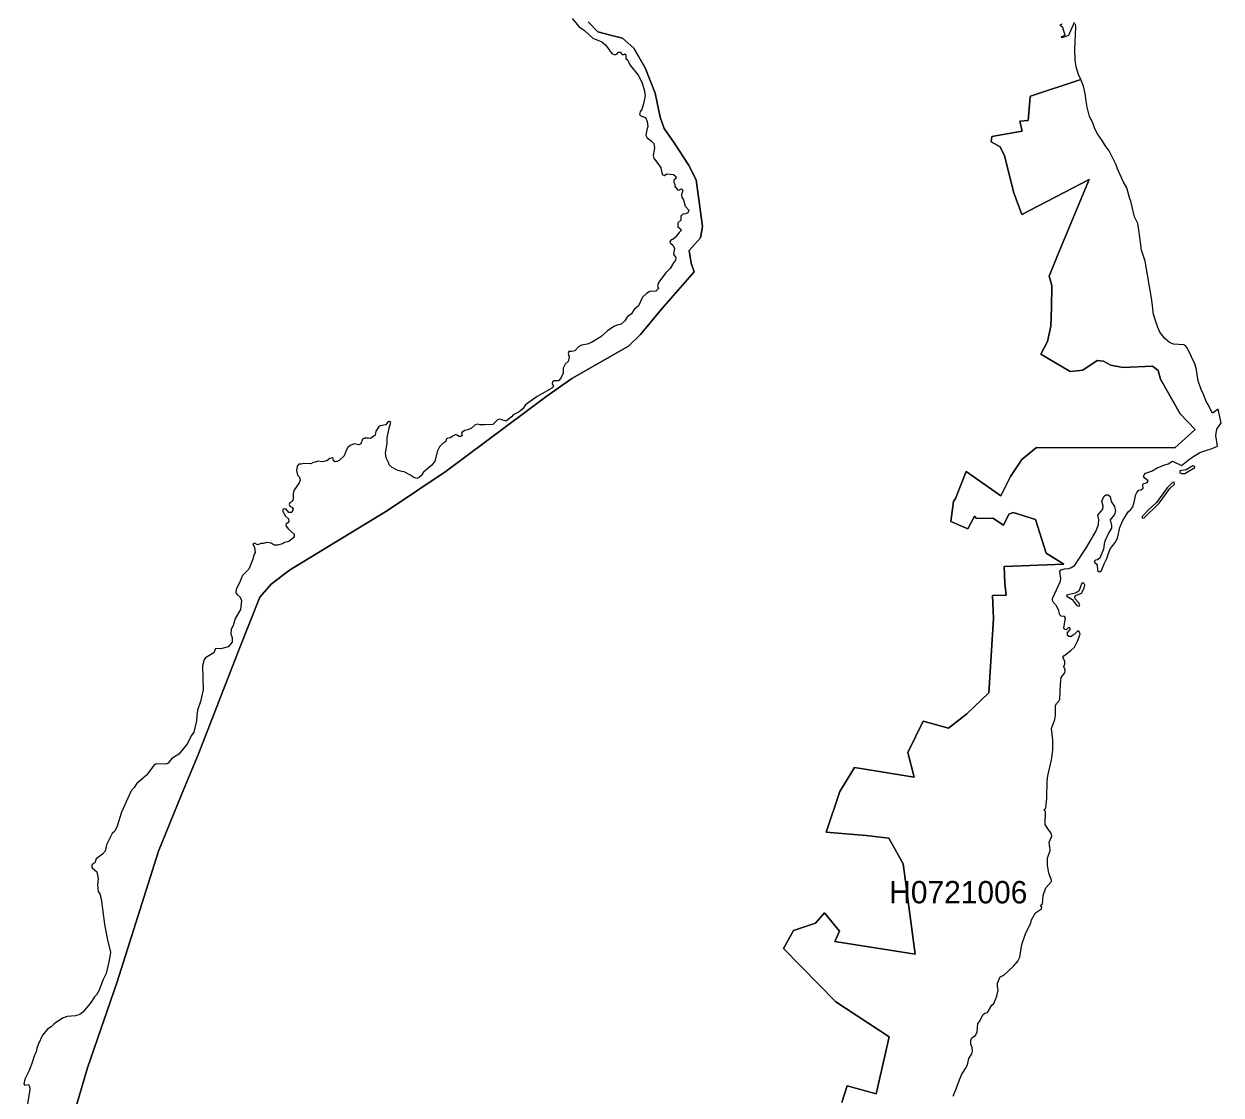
# Model space of a CAD drawing. Extents: x 369010 to 739155, y 6377141 to 6616555.
# Drawn here: x 392519 to 397868, y 6441595 to 6446383 of the extents above; entities that cross this region are included whole.
import ezdxf
from ezdxf.enums import TextEntityAlignment as Align

# ---------------------------------------------------------------- set-up
doc = ezdxf.new("R2010")
doc.units = 0
doc.header["$LTSCALE"] = 40
doc.layers.add('1', color=7, linetype='Continuous', lineweight=13)
doc.layers.add('2', color=7, linetype='Continuous')

msp = doc.modelspace()

# ---------------------------------------------------------------- linework, layer by layer
at = {"layer": '1'}
for points in [[(394968.85, 6446407.72), (395000.13, 6446371.14), (395023.79, 6446353.93), (395061.86, 6446319.18), (395101.08, 6446303.29), (395118.3, 6446289.55), (395145.77, 6446251.15), (395160.17, 6446246.02), (395169.6, 6446250.49), (395175.89, 6446257.77), (395183.84, 6446257.44), (395193.1, 6446247.35), (395199.39, 6446246.85), (395204.52, 6446250), (395208.5, 6446246.02), (395208.17, 6446229.14), (395217.1, 6446221.03), (395227.36, 6446201.01), (395263.77, 6446154.33), (395279.99, 6446123.39), (395290.92, 6446090.78), (395294.89, 6446062.48), (395288.43, 6446026.9), (395279.5, 6446001.24), (395272.05, 6445990.65), (395270.39, 6445979.07), (395275.53, 6445972.78), (395296.71, 6445964.83), (395304.16, 6445947.95), (395306.64, 6445925.28), (395301.84, 6445910.22), (395298.7, 6445886.88), (395303.5, 6445874.14), (395323.52, 6445859.74), (395333.29, 6445848.32), (395337.26, 6445830.28), (395330.97, 6445795.85), (395333.29, 6445783.61), (395341.07, 6445772.68), (395356.79, 6445754.15), (395365.39, 6445740.08), (395371.68, 6445709.96), (395380.79, 6445706.32), (395391.38, 6445713.76), (395407.43, 6445711.11), (395422, 6445709.79), (395432.09, 6445702.01), (395432.92, 6445693.41), (395422.99, 6445685.13), (395422.66, 6445675.86), (395427.13, 6445666.43), (395427.46, 6445658.48), (395438.88, 6445641.93), (395445.5, 6445639.78), (395457.58, 6445646.24), (395463.21, 6445639.62), (395456.75, 6445621.25), (395459.23, 6445608.01), (395467.01, 6445596.92), (395473.3, 6445568.78), (395489.69, 6445551.4), (395485.38, 6445539.65), (395474.79, 6445534.19), (395463.04, 6445532.54), (395454.93, 6445524.76), (395454.1, 6445505.56), (395440.37, 6445494.14), (395440.7, 6445476.43), (395453.28, 6445467.49), (395455.26, 6445459.71), (395446.33, 6445451.77), (395429.28, 6445429.1), (395418.85, 6445420.32), (395410.58, 6445418.5), (395404.62, 6445411.06), (395406.11, 6445404.77), (395419.18, 6445394.51), (395426.63, 6445381.6), (395421.5, 6445352.63), (395431.43, 6445339.89), (395430.93, 6445326.65), (395421.5, 6445316.06), (395406.6, 6445290.07), (395385.42, 6445268.89), (395355.63, 6445228.51), (395350.17, 6445214.44), (395355.3, 6445201.03), (395342.72, 6445189.45), (395315.91, 6445186.63), (395300.68, 6445178.03), (395283.47, 6445161.48), (395265.26, 6445123.58), (395245.4, 6445106.2), (395232.83, 6445086.67)], [(392710.88, 6441402.71), (392803.72, 6441716.34), (392935.3, 6442101.31), (393120.99, 6442685.87), (393221.62, 6442933.79), (393299.08, 6443120.32), (393480.97, 6443588.86), (393573.81, 6443821.22), (393624.13, 6443879.32), (393705.39, 6443941.22), (394144.31, 6444207.51), (394406.3, 6444384.43), (394851.17, 6444715.94), (394967.85, 6444798.03), (395220.41, 6444943.18), (395274.04, 6444994.48), (395368.7, 6445108.02), (395513.85, 6445275.34), (395501.27, 6445313.24), (395491.67, 6445370.18), (395542.15, 6445426.94), (395551.75, 6445477.42), (395522.62, 6445687.12), (395488.03, 6445753.48), (395424.81, 6445851.3), (395380.62, 6445915.68), (395361.75, 6445966.32), (395339.58, 6446073.57), (395295.55, 6446187.27), (395244.91, 6446275.65), (395194.43, 6446319.84), (395140.81, 6446332.58), (395084.04, 6446348.31), (395039.85, 6446392.49)], [(395039.85, 6446392.49), (395084.04, 6446348.31), (395140.81, 6446332.58), (395194.43, 6446319.84), (395244.91, 6446275.65), (395295.55, 6446187.27), (395339.58, 6446073.57), (395361.75, 6445966.32), (395380.62, 6445915.68), (395424.81, 6445851.3), (395488.03, 6445753.48), (395522.62, 6445687.12), (395551.75, 6445477.42), (395542.15, 6445426.94), (395491.67, 6445370.18), (395501.27, 6445313.24), (395513.85, 6445275.34), (395368.7, 6445108.02)], [(397430.06, 6444847.51), (397376.6, 6444857.28), (397342.67, 6444876.15), (397315.53, 6444878.3), (397250.15, 6444834.94), (397193.55, 6444829.47), (397062.8, 6444907.59), (397092.43, 6444964.03), (397107.49, 6445031.89), (397110.8, 6445113.81), (397111.79, 6445214.44), (397100.04, 6445255.32), (397137.28, 6445348.16), (397278.79, 6445687.61), (396978.73, 6445532.04), (396942.65, 6445628.86), (396900.11, 6445793.37), (396880.91, 6445834.25), (396841.52, 6445856.26), (396843.68, 6445880.26), (396979.89, 6445904.09), (396969.13, 6445949.11), (397006.37, 6445952.09), (397015.97, 6446057.85), (397016.3, 6446060.33), (397241.55, 6446134.31), (397232.11, 6446157.64), (397220.69, 6446191.74), (397216.89, 6446221.69), (397215.73, 6446270.68), (397220.03, 6446368.66), (397218.21, 6446384.05)], [(397211.92, 6446389.35), (397186.1, 6446332.42), (397157.14, 6446321.99), (397155.15, 6446327.29), (397172.37, 6446333.91), (397160.29, 6446370.98), (397154.82, 6446371.31), (397150.35, 6446374.45), (397151.18, 6446380.25), (397157.14, 6446382.23), (397158.63, 6446384.88)], [(397241.55, 6446134.31), (397016.3, 6446060.33), (397015.97, 6446057.85), (397006.37, 6445952.09), (396969.13, 6445949.11), (396979.89, 6445904.09), (396843.68, 6445880.26), (396841.52, 6445856.26), (396880.91, 6445834.25), (396900.11, 6445793.37), (396942.65, 6445628.86), (396978.73, 6445532.04), (397278.79, 6445687.61), (397137.28, 6445348.16), (397100.04, 6445255.32), (397111.79, 6445214.44), (397110.8, 6445113.81), (397107.49, 6445031.89), (397092.43, 6444964.03), (397062.8, 6444907.59), (397193.55, 6444829.47), (397250.15, 6444834.94), (397315.53, 6444878.3), (397342.67, 6444876.15), (397376.6, 6444857.28), (397430.06, 6444847.51), (397562.13, 6444853.47), (397587.78, 6444833.94), (397597.55, 6444795.22), (397685.26, 6444640.97), (397753.29, 6444570.13), (397662.09, 6444487.71), (397044.1, 6444489.86), (396977.9, 6444436.07), (396927.42, 6444360.77), (396884.39, 6444273.22), (396729.81, 6444383.28), (396682.31, 6444262.13), (396672.54, 6444248.22), (396661.29, 6444158.85), (396736.26, 6444126.08), (396766.39, 6444182.35), (396776.32, 6444172.59), (396849.3, 6444174.08), (396896.64, 6444142.8), (396920.14, 6444192.45), (396940.16, 6444199.4), (397038.97, 6444168.62), (397087.3, 6444017.51), (397166.24, 6443968.85), (396899.95, 6443957.6), (396902.26, 6443882.3), (396908.55, 6443829.33), (396847.65, 6443827.84), (396852.12, 6443725.56), (396831.43, 6443393.07), (396732.13, 6443299.23), (396649.87, 6443234.84), (396537.82, 6443265.96), (396468.97, 6443126.94), (396497.28, 6443015.39), (396230.81, 6443059.74), (396164.94, 6442952.33), (396104.37, 6442769.78), (396282.95, 6442755.54), (396384.07, 6442743.96), (396447.46, 6442628.44), (396502.08, 6442225.1), (396142.1, 6442280.88), (396162.96, 6442326.89), (396095.93, 6442409.14), (396055.88, 6442363.13), (395957.73, 6442331.03), (395913.05, 6442250.26), (396146.41, 6442012.1), (396385.89, 6441855.86), (396327.97, 6441600.66), (396197.05, 6441635.58), (396173.22, 6441561.93)], [(397374.45, 6444038.2), (397394.64, 6444065.84), (397405.23, 6444084.04), (397415.49, 6444131.88), (397429.89, 6444163.82), (397453.23, 6444202.55), (397465.31, 6444211.98), (397473.75, 6444224.72), (397480.87, 6444244.75), (397487.49, 6444280.33), (397491.79, 6444288.61), (397500.56, 6444298.87), (397512.15, 6444300.19), (397521.08, 6444308.47), (397518.77, 6444318.23), (397520.26, 6444328.16), (397538.96, 6444334.12), (397542.43, 6444340.41), (397521.91, 6444357.95), (397525.06, 6444368.05), (397531.51, 6444374.84), (397557.16, 6444384.27), (397582.49, 6444399), (397617.08, 6444412.4), (397632.3, 6444416.38), (397650.84, 6444428.13), (397691.06, 6444408.76), (397720.85, 6444432.6), (397746.83, 6444451.13), (397772.98, 6444467.68), (397799.96, 6444475.79), (397823.96, 6444483.41), (397853.08, 6444496.32), (397844.98, 6444544.15), (397850.11, 6444571.12), (397868.48, 6444599.76), (397855.4, 6444660.5), (397830.91, 6444643.12), (397809.56, 6444684.16), (397801.61, 6444695.58), (397792.18, 6444723.39), (397780.1, 6444749.04), (397765.7, 6444788.43), (397757.26, 6444844.7), (397751.63, 6444864.07), (397718.86, 6444933.08), (397711.08, 6444942.68), (397701.65, 6444948.14), (397656.14, 6444951.29), (397638.76, 6444958.9), (397616.91, 6444977.1), (397595.56, 6445005.57), (397585.63, 6445025.93), (397567.26, 6445085.18), (397559.32, 6445149.23), (397529.36, 6445322.84), (397513.64, 6445372.16), (397502.88, 6445453.09), (397496.26, 6445490.99), (397481.53, 6445520.79), (397465.47, 6445590.63), (397460.34, 6445601.72), (397447.6, 6445650.37), (397430.72, 6445678.68), (397405.4, 6445735.61), (397400.27, 6445753.15), (397368.65, 6445815.55), (397351.11, 6445839.55), (397337.71, 6445862.55), (397316.69, 6445892.18), (397304.94, 6445915.02), (397295.5, 6445941.17), (397280.94, 6445969.3), (397269.85, 6446010.68), (397263.73, 6446047.09), (397263.06, 6446064.3), (397253.13, 6446105.84), (397241.55, 6446134.31)], [(395368.7, 6445108.02), (395274.04, 6444994.48), (395220.41, 6444943.18), (394967.85, 6444798.03), (394851.17, 6444715.94), (394406.3, 6444384.43), (394144.31, 6444207.51), (393705.39, 6443941.22), (393624.13, 6443879.32), (393573.81, 6443821.22), (393480.97, 6443588.86), (393299.08, 6443120.32), (393221.62, 6442933.79), (393120.99, 6442685.87), (392935.3, 6442101.31), (392803.72, 6441716.34), (392710.88, 6441402.71)], [(395232.83, 6445086.67), (395216.28, 6445075.91), (395203.7, 6445055.72), (395187.64, 6445041.49), (395165.3, 6445035.2), (395155.04, 6445030.4), (395126.57, 6445012.03), (395096.95, 6444984.55), (395055.07, 6444959.56), (395035.88, 6444952.11), (395011.22, 6444947.81), (394997.81, 6444940.2), (394981.26, 6444922.65), (394967.69, 6444918.35), (394953.45, 6444918.35), (394950.64, 6444909.74), (394955.77, 6444893.19), (394951.47, 6444873.66), (394937.73, 6444861.75), (394928.3, 6444844.2), (394928.63, 6444822.19), (394919.03, 6444800.18), (394907.94, 6444787.6), (394885.6, 6444787.27), (394880.8, 6444783.3), (394878.98, 6444775.52), (394886.26, 6444763.11), (394878.48, 6444754.67), (394813.11, 6444718.26), (394760.31, 6444680.19), (394748.56, 6444662.65), (394731.68, 6444648.91), (394705.86, 6444636.33), (394697.75, 6444627.23), (394674.42, 6444606.87), (394646.28, 6444615.97), (394635.36, 6444613.16), (394614.83, 6444591.98), (394600.77, 6444591.48), (394592.16, 6444593.14), (394580.41, 6444591.65), (394556.08, 6444591.15), (394547.31, 6444593.63), (394535.23, 6444591.15), (394519.5, 6444575.92), (394502.29, 6444568.14), (394490.04, 6444565.99), (394477.47, 6444558.71), (394475.15, 6444553.58), (394476.8, 6444542.99), (394471.67, 6444539.02), (394462.57, 6444539.51), (394455.62, 6444545.3), (394448.5, 6444547.29), (394433.94, 6444540.17), (394425, 6444532.73), (394414.08, 6444532.23), (394407.29, 6444528.42), (394403.32, 6444515.02), (394393.89, 6444510.38), (394376.67, 6444492.67), (394367.41, 6444475.13), (394355.82, 6444428.29), (394341.42, 6444411.25), (394304.84, 6444380.13), (394297.4, 6444366.39), (394285.65, 6444356.13), (394274.72, 6444350.84), (394260.99, 6444356.3), (394243.77, 6444368.05), (394217.79, 6444381.79), (394208.02, 6444382.61), (394187.17, 6444389.23), (394164.83, 6444400.99), (394151.59, 6444412.24), (394148.77, 6444423.33), (394137.69, 6444444.02), (394134.71, 6444464.54), (394141.66, 6444507.57), (394142.82, 6444533.06), (394150.93, 6444575.92), (394158.37, 6444602.07), (394152.08, 6444606.54), (394145.46, 6444605.22), (394136.36, 6444591.15), (394111.7, 6444587.18), (394103.43, 6444580.89), (394092.17, 6444562.19), (394089.03, 6444545.64), (394067.84, 6444529.91), (394057.09, 6444532.23), (394043.02, 6444532.23), (394032.09, 6444526.44), (394024.15, 6444506.91), (394016.04, 6444502.11), (393994.36, 6444505.75), (393976.65, 6444499.46), (393966.89, 6444490.36), (393959.77, 6444476.95), (393950, 6444452.79)], [(396173.22, 6441561.93), (396197.05, 6441635.58), (396327.97, 6441600.66), (396385.89, 6441855.86), (396146.41, 6442012.1), (395913.05, 6442250.26), (395957.73, 6442331.03), (396055.88, 6442363.13), (396095.93, 6442409.14), (396162.96, 6442326.89), (396142.1, 6442280.88), (396502.08, 6442225.1), (396447.46, 6442628.44), (396384.07, 6442743.96), (396282.95, 6442755.54), (396104.37, 6442769.78), (396164.94, 6442952.33), (396230.81, 6443059.74), (396497.28, 6443015.39), (396468.97, 6443126.94), (396537.82, 6443265.96), (396649.87, 6443234.84), (396732.13, 6443299.23), (396831.43, 6443393.07), (396852.12, 6443725.56), (396847.65, 6443827.84), (396908.55, 6443829.33), (396902.26, 6443882.3), (396899.95, 6443957.6), (397166.24, 6443968.85), (397087.3, 6444017.51), (397038.97, 6444168.62), (396940.16, 6444199.4), (396920.14, 6444192.45), (396896.64, 6444142.8), (396849.3, 6444174.08), (396776.32, 6444172.59), (396766.39, 6444182.35), (396736.26, 6444126.08), (396661.29, 6444158.85), (396672.54, 6444248.22), (396682.31, 6444262.13), (396729.81, 6444383.28), (396884.39, 6444273.22), (396927.42, 6444360.77), (396977.9, 6444436.07), (397044.1, 6444489.86), (397662.09, 6444487.71), (397753.29, 6444570.13), (397685.26, 6444640.97), (397597.55, 6444795.22), (397587.78, 6444833.94), (397562.13, 6444853.47), (397430.06, 6444847.51)], [(393950, 6444452.79), (393928.49, 6444432.27), (393917.57, 6444426.8), (393910.12, 6444426.47), (393902.67, 6444430.28), (393901.35, 6444441.37), (393896.38, 6444444.02), (393886.12, 6444441.04), (393872.71, 6444429.62), (393852.03, 6444425.98), (393833.16, 6444428.79), (393822.57, 6444424.16), (393811.64, 6444423.33), (393800.88, 6444417.37), (393769.27, 6444417.87), (393757.69, 6444415.38), (393748.09, 6444415.05), (393739.65, 6444406.45), (393737.83, 6444384.93), (393740.97, 6444366.39), (393751.07, 6444356.96), (393753.88, 6444344.05), (393748.42, 6444331.47), (393725.58, 6444297.88), (393721.77, 6444284.14), (393721.77, 6444258.49), (393717.31, 6444248.39), (393707.54, 6444242.43), (393704.07, 6444234.98), (393707.87, 6444227.87), (393718.46, 6444221.58), (393722.44, 6444213.47), (393716.15, 6444199.73), (393702.91, 6444198.9), (393689.17, 6444215.46), (393677.75, 6444214.3), (393675.1, 6444206.85), (393688.67, 6444182.35), (393702.08, 6444170.27), (393703.24, 6444159.02), (393698.44, 6444152.56), (393690.66, 6444148.43), (393689.83, 6444138.99), (393701.25, 6444125.09), (393726.08, 6444102.75), (393727.24, 6444089.51), (393703.24, 6444070.31), (393683.71, 6444065.18), (393674.94, 6444059.22), (393652.26, 6444053.1), (393637.7, 6444053.76), (393624.29, 6444061.54), (393604.43, 6444064.85), (393588.71, 6444060.87), (393578.78, 6444060.05), (393563.22, 6444055.41), (393549.15, 6444062.53), (393542.37, 6444059.22), (393549.15, 6444042.34), (393551.8, 6444021.15), (393548.33, 6444013.71), (393542.04, 6443990.7), (393523.5, 6443946.68), (393496.19, 6443918.04), (393481.3, 6443881.14), (393467.89, 6443856.48), (393466.73, 6443839.6), (393471.37, 6443832.48), (393485.6, 6443820.4), (393491.06, 6443805.17), (393486.26, 6443765.12), (393463.59, 6443725.89), (393454.49, 6443694.78), (393445.05, 6443677.24), (393444.22, 6443655.56), (393450.35, 6443640.83), (393450.35, 6443619.64), (393431.65, 6443599.12), (393399.04, 6443589.35), (393375.87, 6443592), (393367.6, 6443571.31), (393331.02, 6443549.8), (393324.07, 6443541.85), (393317.28, 6443513.55), (393320.1, 6443406.47), (393308.35, 6443354.67), (393295.1, 6443315.11), (393291.79, 6443290.12), (393290.64, 6443267.61), (393278.22, 6443216.64), (393267.13, 6443201.08), (393249.43, 6443167.32), (393232.71, 6443143.82), (393210.7, 6443118.99), (393179.58, 6443100.12), (393164.03, 6443078.61), (393153.43, 6443074.31), (393109.74, 6443075.13), (393099.15, 6443068.51), (393066.21, 6443024.49)], [(397094.08, 6442785.34), (397082.66, 6442805.03), (397083.82, 6442861.96), (397075.88, 6442870.24), (397085.15, 6442877.36), (397089.45, 6442921.88), (397092.1, 6443000.32), (397094.91, 6443021.84), (397110.8, 6443094.17), (397117.42, 6443137.36), (397117.09, 6443183.21), (397110.8, 6443234.18), (397125.69, 6443274.07), (397129.17, 6443291.45), (397128.18, 6443310.31), (397129.34, 6443336.46), (397134.47, 6443347.55), (397143.4, 6443355.83), (397147.38, 6443364.1), (397150.85, 6443431.63), (397154, 6443462.08), (397169.72, 6443483.1), (397171.7, 6443494.85), (397165.75, 6443511.07), (397170.22, 6443521.83), (397170.55, 6443535.07), (397163.76, 6443544.67), (397161.61, 6443553.27), (397165.91, 6443558.9), (397197.52, 6443581.91), (397213.25, 6443597.13), (397226.98, 6443624.44), (397238.24, 6443655.72), (397234.6, 6443667.47), (397227.98, 6443670.62), (397211.59, 6443654.07), (397199.34, 6443644.96), (397189.91, 6443644.96), (397182.79, 6443649.43), (397182.79, 6443661.68), (397195.37, 6443678.89), (397191.9, 6443684.85), (397185.61, 6443684.19), (397176.01, 6443675.08), (397168.89, 6443676.24), (397165.42, 6443683.69), (397172.7, 6443727.22), (397168.89, 6443734.67), (397154.16, 6443735.99), (397148.7, 6443741.78), (397144.23, 6443759.16), (397133.14, 6443781.67), (397119.07, 6443796.4), (397115.76, 6443805.5), (397115.76, 6443815.43), (397151.35, 6443891.56), (397151.84, 6443903.81), (397147.87, 6443936.25), (397153, 6443942.54), (397169.55, 6443948.17), (397186.27, 6443948.5), (397200.83, 6443952.8), (397214.57, 6443963.56), (397267.04, 6444042.5), (397310.07, 6444117.15), (397320.33, 6444145.61), (397322.31, 6444167.79), (397318.01, 6444187.65), (397339.69, 6444214.13), (397341.35, 6444227.37), (397335.39, 6444249.22), (397345.32, 6444271.4), (397354.26, 6444278.84), (397363.36, 6444278.51), (397373.29, 6444271.23), (397376.93, 6444247.89), (397391.66, 6444225.55), (397397.12, 6444205.36), (397392.82, 6444190.8), (397372.3, 6444166.63), (397378.75, 6444140.48), (397378.58, 6444128.57), (397365.68, 6444106.22), (397349.46, 6444071.8), (397345.82, 6444057.9), (397343, 6444035.06), (397326.12, 6443995.83), (397315.86, 6443987.56), (397307.42, 6443986.07), (397302.29, 6443982.09), (397302.78, 6443977.29), (397314.2, 6443967.53), (397317.02, 6443940.55), (397323.31, 6443934.59), (397328.93, 6443935.42), (397334.06, 6443939.73), (397345.82, 6443969.85), (397357.73, 6443994.01), (397367.83, 6444025.46), (397374.45, 6444038.2)], [(393066.21, 6443024.49), (393022.35, 6442986.09), (393011.43, 6442969.87), (392998.52, 6442954.31), (392955.33, 6442858.98), (392935.3, 6442797.42), (392924.71, 6442775.4), (392914.11, 6442764.15), (392888.63, 6442714.17), (392881.51, 6442685.54), (392870.42, 6442672.3), (392842.62, 6442650.78), (392836.49, 6442633.73), (392828.55, 6442629.43), (392821.1, 6442621.65), (392824.58, 6442611.39), (392844.27, 6442592.19), (392850.89, 6442562.73), (392847.42, 6442534.27), (392850.89, 6442505.63), (392858.67, 6442494.88), (392864.13, 6442472.53), (392878.7, 6442358.17), (392891.11, 6442294.12), (392906.5, 6442233.71), (392900.54, 6442196.14), (392886.81, 6442137.72), (392871.58, 6442107.93), (392854.7, 6442063.41), (392842.95, 6442042.72), (392834.67, 6442034.11), (392815.47, 6442004.65), (392782.04, 6441965.43), (392769.13, 6441955.66), (392749.93, 6441948.88), (392713.03, 6441946.56), (392691.84, 6441938.29), (392654.27, 6441912.8), (392640.37, 6441899.56), (392624.81, 6441889.63), (392601.64, 6441863.15), (392582.44, 6441820.78), (392576.49, 6441803.9), (392573.34, 6441788.84), (392565.89, 6441773.28), (392554.97, 6441736.37), (392540.74, 6441701.12), (392523.53, 6441666.2), (392519.22, 6441644.52), (392523.53, 6441639.55), (392538.92, 6441641.7), (392544.71, 6441632.43), (392545.04, 6441620.19), (392525.84, 6441500.69)], [(396670.89, 6441589.73), (396685.12, 6441622.17), (396699.52, 6441663.38), (396708.96, 6441685.4), (396726.5, 6441713.03), (396734.77, 6441729.92), (396740.9, 6441758.05), (396754.14, 6441778.91), (396757.45, 6441791.32), (396756.29, 6441807.7), (396750, 6441822.43), (396750.33, 6441841.8), (396756.62, 6441852.89), (396771.68, 6441861.66), (396778.47, 6441878.04), (396782.27, 6441914.62), (396789.39, 6441923.56), (396805.28, 6441954.84), (396813.55, 6441960.63), (396824.97, 6441963.94), (396844.01, 6441996.21), (396853.11, 6442004.65), (396866.85, 6442037.75), (396872.47, 6442063.41), (396869.16, 6442080.95), (396869.66, 6442095.51), (396881.41, 6442123.82), (396898.46, 6442130.27), (396940.5, 6442170.98), (396961.02, 6442193), (396969.62, 6442211.53), (396978.23, 6442268.14), (396994.62, 6442315.97), (397019.11, 6442364.62), (397022.09, 6442378.03), (397039.14, 6442410.3), (397065.95, 6442427.02), (397066.94, 6442434.47), (397060.98, 6442441.91), (397070.75, 6442449.53), (397073.56, 6442486.6), (397085.48, 6442521.85), (397110.3, 6442549.33), (397111.13, 6442556.11), (397098.39, 6442586.9), (397092.26, 6442622.15), (397093.26, 6442654.09), (397104.51, 6442688.18), (397103.52, 6442703.58), (397100.04, 6442724.93), (397111.63, 6442751.74), (397109.64, 6442766.3), (397094.08, 6442785.34)]]:
    msp.add_lwpolyline(points, dxfattribs=at)
for points in [[(397742.86, 6444407.94), (397713.23, 6444389.73), (397683.94, 6444385.59), (397683.94, 6444377.15), (397692.38, 6444373.18), (397706.78, 6444373.68), (397751.96, 6444400.16), (397750.8, 6444405.62)], [(397659.11, 6444335.28), (397651.17, 6444333.46), (397627.5, 6444309.3), (397580.17, 6444243.59), (397544.25, 6444211.65), (397516.28, 6444180.7), (397515.29, 6444174.58), (397525.39, 6444175.24), (397591.42, 6444241.27), (397640.08, 6444307.31), (397660.27, 6444326.18)], [(397246.84, 6443883.62), (397233.44, 6443847.71), (397218.05, 6443838.27), (397177.99, 6443830.33), (397179.65, 6443824.7), (397203.48, 6443810.63), (397224, 6443783.32), (397234.27, 6443780.84), (397237.74, 6443786.14), (397231.45, 6443797.56), (397216.39, 6443813.45), (397214.74, 6443822.88), (397218.87, 6443828.34), (397245.35, 6443838.93), (397257.1, 6443860.45), (397259.59, 6443875.01), (397255.95, 6443882.96)]]:
    msp.add_lwpolyline(points, close=True, dxfattribs=at)

# ---------------------------------------------------------------- texts
at = {"layer": '2'}
msp.add_text('H0721006', height=100, dxfattribs=at).set_placement((396694.28, 6442451.91), align=Align.CENTER)

doc.saveas('drawing.dxf')
